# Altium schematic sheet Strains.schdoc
size 159 x 381 mm
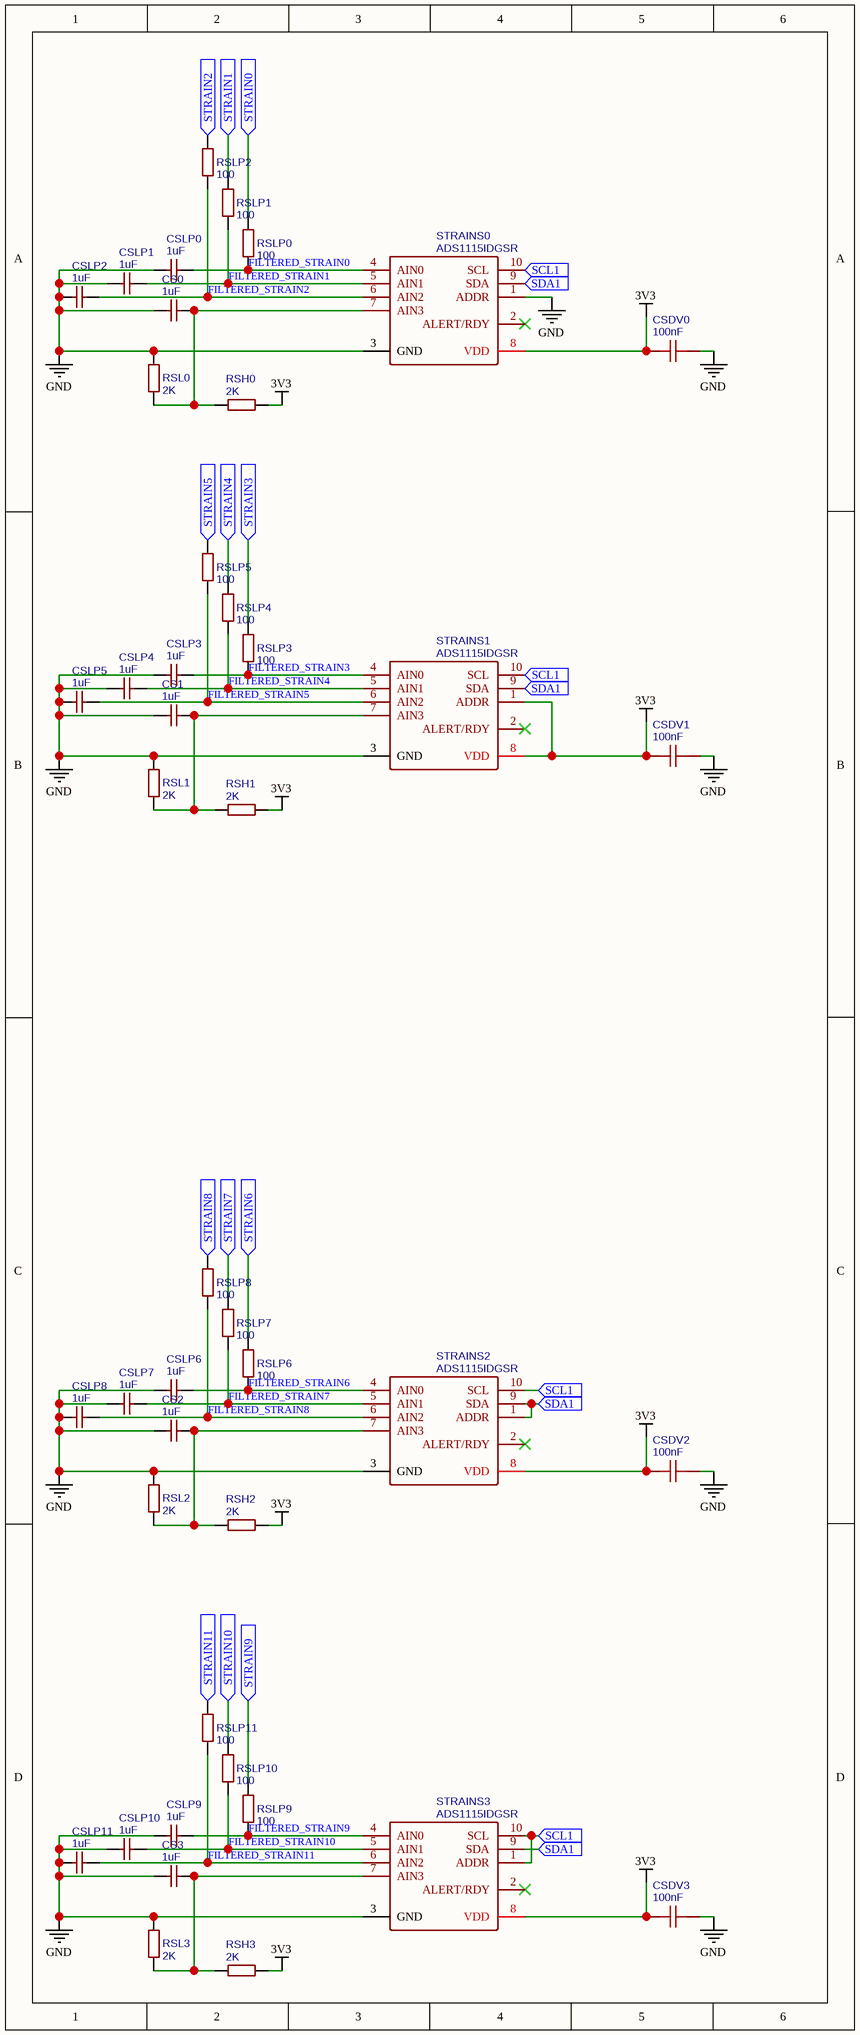
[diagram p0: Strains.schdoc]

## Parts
CS0  1uF  [0603]
CS1  1uF  [0603]
CS2  1uF  [0603]
CS3  1uF  [0603]
CSDV0  100nF  [0603]
CSDV1  100nF  [0603]
CSDV2  100nF  [0603]
CSDV3  100nF  [0603]
CSLP0  1uF  [0603]
CSLP1  1uF  [0603]
CSLP2  1uF  [0603]
CSLP3  1uF  [0603]
CSLP4  1uF  [0603]
CSLP5  1uF  [0603]
CSLP6  1uF  [0603]
CSLP7  1uF  [0603]
CSLP8  1uF  [0603]
CSLP9  1uF  [0603]
CSLP10  1uF  [0603]
CSLP11  1uF  [0603]
RSH0  2K  [0603]
RSH1  2K  [0603]
RSH2  2K  [0603]
RSH3  2K  [0603]
RSL0  2K  [0603]
RSL1  2K  [0603]
RSL2  2K  [0603]
RSL3  2K  [0603]
RSLP0  100  [0603]
RSLP1  100  [0603]
RSLP2  100  [0603]
RSLP3  100  [0603]
RSLP4  100  [0603]
RSLP5  100  [0603]
RSLP6  100  [0603]
RSLP7  100  [0603]
RSLP8  100  [0603]
RSLP9  100  [0603]
RSLP10  100  [0603]
RSLP11  100  [0603]
STRAINS0  ADS1115IDGSR  [MSOP-10-DOT-BOT-LEFT]
STRAINS1  ADS1115IDGSR  [MSOP-10-DOT-BOT-LEFT]
STRAINS2  ADS1115IDGSR  [MSOP-10-DOT-BOT-LEFT]
STRAINS3  ADS1115IDGSR  [MSOP-10-DOT-BOT-LEFT]

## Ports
SCL1, SDA1, STRAIN0, STRAIN1, STRAIN2, STRAIN3, STRAIN4, STRAIN5, STRAIN6, STRAIN7, STRAIN8, STRAIN9, STRAIN10, STRAIN11

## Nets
3V3: CSDV0.2 CSDV1.2 CSDV2.2 CSDV3.2 RSH0.1 RSH1.1 RSH2.1 RSH3.1 STRAINS0.8(VDD) STRAINS1.1(ADDR) STRAINS1.8(VDD) STRAINS2.8(VDD) STRAINS3.8(VDD)
GND: CS0.2 CS1.2 CS2.2 CS3.2 CSDV0.1 CSDV1.1 CSDV2.1 CSDV3.1 CSLP0.1 CSLP1.1 CSLP2.1 CSLP3.1 CSLP4.1 CSLP5.1 CSLP6.1 CSLP7.1 CSLP8.1 CSLP9.1 CSLP10.1 CSLP11.1 RSL0.2 RSL1.2 RSL2.2 RSL3.2 STRAINS0.1(ADDR) STRAINS0.3(GND) STRAINS1.3(GND) STRAINS2.3(GND) STRAINS3.3(GND)
FILTERED_STRAIN0: CSLP0.2 RSLP0.2 STRAINS0.4(AIN0)
FILTERED_STRAIN1: CSLP1.2 RSLP1.2 STRAINS0.5(AIN1)
FILTERED_STRAIN2: CSLP2.2 RSLP2.2 STRAINS0.6(AIN2)
FILTERED_STRAIN3: CSLP3.2 RSLP3.2 STRAINS1.4(AIN0)
FILTERED_STRAIN4: CSLP4.2 RSLP4.2 STRAINS1.5(AIN1)
FILTERED_STRAIN5: CSLP5.2 RSLP5.2 STRAINS1.6(AIN2)
FILTERED_STRAIN6: CSLP6.2 RSLP6.2 STRAINS2.4(AIN0)
FILTERED_STRAIN7: CSLP7.2 RSLP7.2 STRAINS2.5(AIN1)
FILTERED_STRAIN8: CSLP8.2 RSLP8.2 STRAINS2.6(AIN2)
FILTERED_STRAIN9: CSLP9.2 RSLP9.2 STRAINS3.4(AIN0)
FILTERED_STRAIN10: CSLP10.2 RSLP10.2 STRAINS3.5(AIN1)
FILTERED_STRAIN11: CSLP11.2 RSLP11.2 STRAINS3.6(AIN2)
SCL1: STRAINS0.10(SCL) STRAINS1.10(SCL) STRAINS2.10(SCL) STRAINS3.1(ADDR) STRAINS3.10(SCL) ; port SCL1
SDA1: STRAINS0.9(SDA) STRAINS1.9(SDA) STRAINS2.1(ADDR) STRAINS2.9(SDA) STRAINS3.9(SDA) ; port SDA1
STRAIN0: RSLP0.1 ; port STRAIN0
STRAIN1: RSLP1.1 ; port STRAIN1
STRAIN2: RSLP2.1 ; port STRAIN2
STRAIN3: RSLP3.1 ; port STRAIN3
STRAIN4: RSLP4.1 ; port STRAIN4
STRAIN5: RSLP5.1 ; port STRAIN5
STRAIN6: RSLP6.1 ; port STRAIN6
STRAIN7: RSLP7.1 ; port STRAIN7
STRAIN8: RSLP8.1 ; port STRAIN8
STRAIN9: RSLP9.1 ; port STRAIN9
STRAIN10: RSLP10.1 ; port STRAIN10
STRAIN11: RSLP11.1 ; port STRAIN11
NetCS0_1: CS0.1 RSH0.2 RSL0.1 STRAINS0.7(AIN3)
NetCS1_1: CS1.1 RSH1.2 RSL1.1 STRAINS1.7(AIN3)
NetCS2_1: CS2.1 RSH2.2 RSL2.1 STRAINS2.7(AIN3)
NetCS3_1: CS3.1 RSH3.2 RSL3.1 STRAINS3.7(AIN3)

Not connected (* = marked no-connect by the designer): STRAINS0 2(ALERT/RDY)*; STRAINS1 2(ALERT/RDY)*; STRAINS2 2(ALERT/RDY)*; STRAINS3 2(ALERT/RDY)*

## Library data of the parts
CS0-CS3 CSLP0-CSLP11 = 1uF: BOM_Manufacturer Part: CL10A105KB8NNNC; BOM_Manufacturer: SAMSUNG; nameAlias: Capacitance; SMT Type: Basic
CSDV0-CSDV3 = 100nF: BOM_Manufacturer: YAGEO; BOM_Manufacturer Part: CC0603KRX7R9BB104; nameAlias: Capacitance; SMT Type: Basic
RSH0-RSH3 RSL0-RSL3 = 2K: BOM_Manufacturer: UniOhm; BOM_Manufacturer Part: 0603WAF2001T5E; nameAlias: Resistance (Ohms); SMT Type: Basic
RSLP0-RSLP11 = 100: BOM_Manufacturer: UniOhm; BOM_Manufacturer Part: 0603WAF1000T5E; nameAlias: Resistance (Ohms); SMT Type: Basic
STRAINS0-STRAINS3 = ADS1115IDGSR: BOM_Manufacturer: TI; SMT Type: Extend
